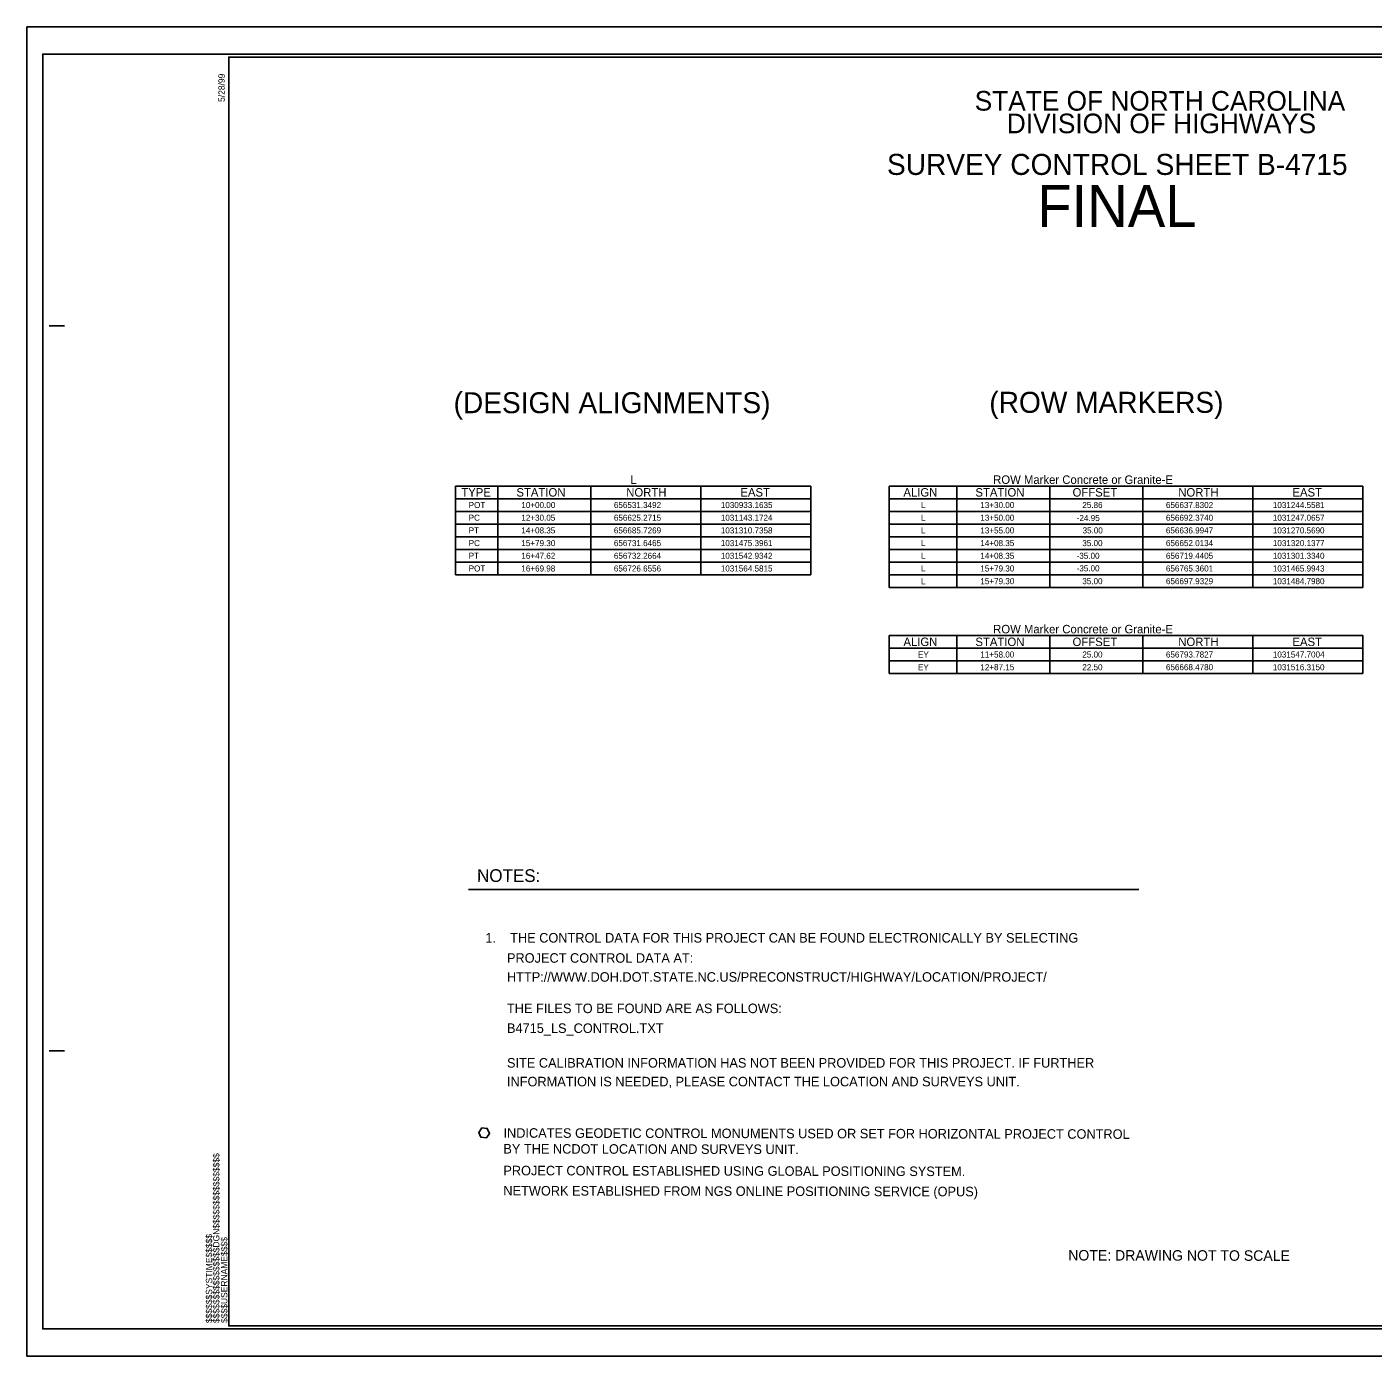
# Model space of a CAD drawing. Extents: x 950817 to 1031536, y 657728 to 805119.
# Drawn here: x 1029852 to 1030966, y 657728 to 658828 of the extents above; entities that cross this region are included whole.
import ezdxf

# ---------------------------------------------------------------- set-up
doc = ezdxf.new("R2010")
doc.units = 0
for name, color, linetype in [('CTL GPS Vertical CELL', 7, 'Continuous'), ('CTL Sheet Border CELL', 7, 'Continuous'), ('CTL Sheet Notes CELL', 7, 'Continuous'), ('CTL Sheet Table Cell', 7, 'Continuous'), ('CTL Sheet Text', 7, 'Continuous'), ('Sheet Cutting Line CELL', 7, 'Continuous'), ('Sheet Plot Border Inside CELL', 7, 'Continuous'), ('Sheet Plot Border Outside CELL', 7, 'Continuous'), ('Sheet Summary CELL', 7, 'Continuous')]:
    doc.layers.add(name, color=color, linetype=linetype)

# ---------------------------------------------------------------- blocks, each defined once
blk = doc.blocks.new('CTL GPS VERTICAL')
at = {"layer": 'CTL GPS Vertical CELL'}
blk.add_line((-0.001, 0), (-0.001, 0), dxfattribs=at)
blk.add_lwpolyline([(-0.065, 0.037), (0, 0.074), (0.065, 0.038), (0.064, -0.036), (-0.001, -0.074), (-0.065, -0.038)], close=True, dxfattribs=at)

msp = doc.modelspace()

# ---------------------------------------------------------------- linework, layer by layer
at = {"layer": 'CTL Sheet Notes CELL'}
msp.add_line((1030217, 658114), (1030771.9, 658114), dxfattribs=at)
at = {"layer": 'CTL Sheet Table Cell'}
for p, q in [((1030206.3, 658447.9), (1030500.3, 658447.9)), ((1030206.3, 658447.9), (1030206.3, 658437.4)), ((1030241.3, 658447.9), (1030241.3, 658437.4)), ((1030318.3, 658447.9), (1030318.3, 658437.4)), ((1030409.3, 658447.9), (1030409.3, 658437.4)), ((1030500.3, 658447.9), (1030500.3, 658437.4)), ((1030565.2, 658447.9), (1030957.2, 658447.9)), ((1030565.2, 658447.9), (1030565.2, 658437.4)), ((1030621.2, 658447.9), (1030621.2, 658437.4)), ((1030698.2, 658447.9), (1030698.2, 658437.4)), ((1030775.2, 658447.9), (1030775.2, 658437.4)), ((1030866.2, 658447.9), (1030866.2, 658437.4)), ((1030957.2, 658447.9), (1030957.2, 658437.4)), ((1030206.3, 658437.4), (1030500.3, 658437.4)), ((1030206.3, 658437.4), (1030206.3, 658426.9)), ((1030241.3, 658437.4), (1030241.3, 658426.9)), ((1030318.3, 658437.4), (1030318.3, 658426.9)), ((1030409.3, 658437.4), (1030409.3, 658426.9)), ((1030500.3, 658437.4), (1030500.3, 658426.9)), ((1030565.2, 658437.4), (1030957.2, 658437.4)), ((1030565.2, 658437.4), (1030565.2, 658426.9)), ((1030621.2, 658437.4), (1030621.2, 658426.9)), ((1030698.2, 658437.4), (1030698.2, 658426.9)), ((1030775.2, 658437.4), (1030775.2, 658426.9)), ((1030866.2, 658437.4), (1030866.2, 658426.9)), ((1030957.2, 658437.4), (1030957.2, 658426.9)), ((1030206.3, 658426.9), (1030500.3, 658426.9)), ((1030206.3, 658426.9), (1030206.3, 658416.4)), ((1030241.3, 658426.9), (1030241.3, 658416.4)), ((1030318.3, 658426.9), (1030318.3, 658416.4)), ((1030409.3, 658426.9), (1030409.3, 658416.4)), ((1030500.3, 658426.9), (1030500.3, 658416.4)), ((1030565.2, 658426.9), (1030957.2, 658426.9)), ((1030565.2, 658426.9), (1030565.2, 658416.4)), ((1030621.2, 658426.9), (1030621.2, 658416.4)), ((1030698.2, 658426.9), (1030698.2, 658416.4)), ((1030775.2, 658426.9), (1030775.2, 658416.4)), ((1030866.2, 658426.9), (1030866.2, 658416.4)), ((1030957.2, 658426.9), (1030957.2, 658416.4)), ((1030206.3, 658416.4), (1030500.3, 658416.4)), ((1030206.3, 658416.4), (1030206.3, 658405.9)), ((1030241.3, 658416.4), (1030241.3, 658405.9)), ((1030318.3, 658416.4), (1030318.3, 658405.9)), ((1030409.3, 658416.4), (1030409.3, 658405.9)), ((1030500.3, 658416.4), (1030500.3, 658405.9)), ((1030565.2, 658416.4), (1030957.2, 658416.4)), ((1030565.2, 658416.4), (1030565.2, 658405.9)), ((1030621.2, 658416.4), (1030621.2, 658405.9)), ((1030698.2, 658416.4), (1030698.2, 658405.9)), ((1030775.2, 658416.4), (1030775.2, 658405.9)), ((1030866.2, 658416.4), (1030866.2, 658405.9)), ((1030957.2, 658416.4), (1030957.2, 658405.9)), ((1030206.3, 658405.9), (1030500.3, 658405.9)), ((1030206.3, 658405.9), (1030206.3, 658395.4)), ((1030241.3, 658405.9), (1030241.3, 658395.4)), ((1030318.3, 658405.9), (1030318.3, 658395.4)), ((1030409.3, 658405.9), (1030409.3, 658395.4)), ((1030500.3, 658405.9), (1030500.3, 658395.4)), ((1030565.2, 658405.9), (1030957.2, 658405.9)), ((1030565.2, 658405.9), (1030565.2, 658395.4)), ((1030621.2, 658405.9), (1030621.2, 658395.4)), ((1030698.2, 658405.9), (1030698.2, 658395.4)), ((1030775.2, 658405.9), (1030775.2, 658395.4)), ((1030866.2, 658405.9), (1030866.2, 658395.4)), ((1030957.2, 658405.9), (1030957.2, 658395.4)), ((1030206.3, 658395.4), (1030500.3, 658395.4)), ((1030206.3, 658395.4), (1030206.3, 658384.9)), ((1030241.3, 658395.4), (1030241.3, 658384.9)), ((1030318.3, 658395.4), (1030318.3, 658384.9)), ((1030409.3, 658395.4), (1030409.3, 658384.9)), ((1030500.3, 658395.4), (1030500.3, 658384.9)), ((1030565.2, 658395.4), (1030957.2, 658395.4)), ((1030565.2, 658395.4), (1030565.2, 658384.9)), ((1030621.2, 658395.4), (1030621.2, 658384.9)), ((1030698.2, 658395.4), (1030698.2, 658384.9)), ((1030775.2, 658395.4), (1030775.2, 658384.9)), ((1030866.2, 658395.4), (1030866.2, 658384.9)), ((1030957.2, 658395.4), (1030957.2, 658384.9)), ((1030206.3, 658384.9), (1030500.3, 658384.9)), ((1030206.3, 658384.9), (1030206.3, 658374.4)), ((1030241.3, 658384.9), (1030241.3, 658374.4)), ((1030318.3, 658384.9), (1030318.3, 658374.4)), ((1030409.3, 658384.9), (1030409.3, 658374.4)), ((1030500.3, 658384.9), (1030500.3, 658374.4)), ((1030565.2, 658384.9), (1030957.2, 658384.9)), ((1030565.2, 658384.9), (1030565.2, 658374.4)), ((1030621.2, 658384.9), (1030621.2, 658374.4)), ((1030698.2, 658384.9), (1030698.2, 658374.4)), ((1030775.2, 658384.9), (1030775.2, 658374.4)), ((1030866.2, 658384.9), (1030866.2, 658374.4)), ((1030957.2, 658384.9), (1030957.2, 658374.4)), ((1030206.3, 658374.4), (1030500.3, 658374.4)), ((1030565.2, 658374.4), (1030957.2, 658374.4)), ((1030565.2, 658374.4), (1030565.2, 658363.9)), ((1030621.2, 658374.4), (1030621.2, 658363.9)), ((1030698.2, 658374.4), (1030698.2, 658363.9)), ((1030775.2, 658374.4), (1030775.2, 658363.9)), ((1030866.2, 658374.4), (1030866.2, 658363.9)), ((1030957.2, 658374.4), (1030957.2, 658363.9)), ((1030565.2, 658363.9), (1030957.2, 658363.9)), ((1030565.2, 658324.2), (1030957.2, 658324.2)), ((1030565.2, 658324.2), (1030565.2, 658313.7)), ((1030621.2, 658324.2), (1030621.2, 658313.7)), ((1030698.2, 658324.2), (1030698.2, 658313.7)), ((1030775.2, 658324.2), (1030775.2, 658313.7)), ((1030866.2, 658324.2), (1030866.2, 658313.7)), ((1030957.2, 658324.2), (1030957.2, 658313.7)), ((1030565.2, 658313.7), (1030957.2, 658313.7)), ((1030565.2, 658313.7), (1030565.2, 658303.2)), ((1030621.2, 658313.7), (1030621.2, 658303.2)), ((1030698.2, 658313.7), (1030698.2, 658303.2)), ((1030775.2, 658313.7), (1030775.2, 658303.2)), ((1030866.2, 658313.7), (1030866.2, 658303.2)), ((1030957.2, 658313.7), (1030957.2, 658303.2)), ((1030565.2, 658303.2), (1030957.2, 658303.2)), ((1030565.2, 658303.2), (1030565.2, 658292.7)), ((1030621.2, 658303.2), (1030621.2, 658292.7)), ((1030698.2, 658303.2), (1030698.2, 658292.7)), ((1030775.2, 658303.2), (1030775.2, 658292.7)), ((1030866.2, 658303.2), (1030866.2, 658292.7)), ((1030957.2, 658303.2), (1030957.2, 658292.7)), ((1030565.2, 658292.7), (1030957.2, 658292.7))]:
    msp.add_line(p, q, dxfattribs=at)
at = {"layer": 'Sheet Cutting Line CELL'}
for p, q in [((1031535.6, 658827.9), (1029851.6, 658827.9)), ((1029851.6, 658827.9), (1029851.6, 657727.9)), ((1029851.6, 657727.9), (1031535.6, 657727.9))]:
    msp.add_line(p, q, dxfattribs=at)
at = {"layer": 'Sheet Plot Border Inside CELL'}
msp.add_lwpolyline([(1031531.1, 658805.4), (1029864.6, 658805.4), (1029864.6, 657750.3), (1031531.1, 657750.3)], close=True, dxfattribs=at)
at = {"layer": 'Sheet Plot Border Outside CELL'}
msp.add_lwpolyline([(1031535.6, 658827.9), (1029851.6, 658827.9), (1029851.6, 657727.9), (1031535.6, 657727.9)], close=True, dxfattribs=at)
at = {"layer": 'Sheet Summary CELL'}
for p, q in [((1030018.6, 658802.9), (1030018.6, 658762.4)), ((1030768.2, 658714.1), (1030768.2, 658714.1)), ((1029870.1, 658580.4), (1029882.6, 658580.4)), ((1029870.1, 657980.4), (1029882.6, 657980.4)), ((1030018.6, 657752.9), (1030018.6, 657752.9)), ((1030018.6, 657752.9), (1030018.6, 657752.9)), ((1030018.6, 657752.9), (1030018.6, 657752.9)), ((1030018.6, 657752.9), (1030018.6, 657752.9)), ((1030018.6, 657752.9), (1030018.6, 657752.9)), ((1030018.6, 657752.9), (1030018.6, 657752.9))]:
    msp.add_line(p, q, dxfattribs=at)
msp.add_lwpolyline([(1031518.6, 658802.9), (1030018.6, 658802.9), (1030018.6, 657752.9), (1031518.6, 657752.9)], close=True, dxfattribs=at)
msp.add_lwpolyline([(1030156.1, 657752.9), (1030156.1, 657752.9)], dxfattribs=at)

# ---------------------------------------------------------------- block references
at = {"layer": 'CTL GPS Vertical CELL', "xscale": 60.500000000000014, "yscale": 60.5, "rotation": -35.82530000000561}
msp.add_blockref('CTL GPS VERTICAL', (1030230, 657912.6), dxfattribs=at)

# ---------------------------------------------------------------- texts
at = {"layer": 'CTL Sheet Border CELL'}
for s, height, p in [('SURVEY CONTROL SHEET B-4715', 17.391, (1030563.4, 658705.4)), ('FINAL', 34.78, (1030687.8, 658662.4)), ('(DESIGN ALIGNMENTS)', 17.391, (1030204.7, 658508.2)), ('(ROW MARKERS)', 17.391, (1030648.1, 658508.5))]:
    msp.add_text(s, height=height, dxfattribs=at).set_placement(p)
msp.add_text('NOTE: DRAWING NOT TO SCALE', height=8.696, rotation=359.8948, dxfattribs=at).set_placement((1030713.4, 657807))
at = {"layer": 'CTL Sheet Notes CELL'}
for s, p in [('L', (1030351, 658449.7)), ('ROW Marker Concrete or Granite-E', (1030651.3, 658449.7)), ('TYPE', (1030211.1, 658439.2)), ('STATION', (1030256.7, 658439.2)), ('NORTH', (1030347.6, 658439.2)), ('EAST', (1030442.1, 658439.2)), ('ALIGN', (1030577, 658439.2)), ('STATION', (1030636.6, 658439.2)), ('OFFSET', (1030717, 658439.2)), ('NORTH', (1030804.5, 658439.2)), ('EAST', (1030899, 658439.2)), ('ROW Marker Concrete or Granite-E', (1030651.3, 658326)), ('ALIGN', (1030577, 658315.5)), ('STATION', (1030636.6, 658315.5)), ('OFFSET', (1030717, 658315.5)), ('NORTH', (1030804.5, 658315.5)), ('EAST', (1030899, 658315.5))]:
    msp.add_text(s, height=7, dxfattribs=at).set_placement(p)
for s, height, rotation, p in [('NOTES:', 10.52, 359.8948, (1030224.1, 658120.3)), ('1.    THE CONTROL DATA FOR THIS PROJECT CAN BE FOUND ELECTRONICALLY BY SELECTING', 7.891, 360, (1030231, 658070.1)), ('PROJECT CONTROL DATA AT:', 7.891, 360, (1030248.9, 658053.4)), ('HTTP://WWW.DOH.DOT.STATE.NC.US/PRECONSTRUCT/HIGHWAY/LOCATION/PROJECT/', 7.891, 360, (1030248.9, 658037.7)), ('THE FILES TO BE FOUND ARE AS FOLLOWS:', 7.891, 360, (1030248.9, 658011.7)), ('B4715_LS_CONTROL.TXT', 7.891, 360, (1030248.9, 657995.3)), ('SITE CALIBRATION INFORMATION HAS NOT BEEN PROVIDED FOR THIS PROJECT. IF FURTHER', 7.891, 360, (1030248.9, 657966.6)), ('INFORMATION IS NEEDED, PLEASE CONTACT THE LOCATION AND SURVEYS UNIT.', 7.891, 360, (1030248.9, 657951.1)), ('INDICATES GEODETIC CONTROL MONUMENTS USED OR SET FOR HORIZONTAL PROJECT CONTROL', 7.891, 359.8948, (1030246, 657908.6)), ('BY THE NCDOT LOCATION AND SURVEYS UNIT.', 7.891, 359.8948, (1030245.9, 657895.5)), ('PROJECT CONTROL ESTABLISHED USING GLOBAL POSITIONING SYSTEM.', 7.891, 359.8948, (1030245.9, 657877.5)), ('NETWORK ESTABLISHED FROM NGS ONLINE POSITIONING SERVICE (OPUS)', 7.891, 359.8948, (1030245.9, 657860.8))]:
    msp.add_text(s, height=height, rotation=rotation, dxfattribs=at).set_placement(p)
at = {"layer": 'CTL Sheet Text'}
for s, p in [('POT', (1030217.2, 658429.7)), ('10+00.00', (1030260.8, 658429.7)), ('656531.3492', (1030337.4, 658429.7)), ('1030933.1635', (1030425.9, 658429.7)), ('L', (1030591.6, 658429.7)), ('13+30.00', (1030640.7, 658429.7)), ('25.86', (1030725.1, 658429.7)), ('656637.8302', (1030794.3, 658429.7)), ('1031244.5581', (1030882.8, 658429.7)), ('PC ', (1030217.2, 658419.2)), ('PT ', (1030217.2, 658408.7)), ('12+30.05', (1030260.8, 658419.2)), ('14+08.35', (1030260.8, 658408.7)), ('656625.2715', (1030337.4, 658419.2)), ('656685.7269', (1030337.4, 658408.7)), ('1031143.1724', (1030425.9, 658419.2)), ('1031310.7358', (1030425.9, 658408.7)), ('L', (1030591.6, 658419.2)), ('L', (1030591.6, 658408.7)), ('13+50.00', (1030640.7, 658419.2)), ('13+55.00', (1030640.7, 658408.7)), ('-24.95', (1030720.5, 658419)), ('35.00', (1030725.3, 658408.7)), ('656692.3740', (1030794.3, 658419.2)), ('656636.9947', (1030794.3, 658408.7)), ('1031247.0657', (1030882.8, 658419.2)), ('1031270.5690', (1030882.8, 658408.7)), ('PC ', (1030217.2, 658398.2)), ('15+79.30', (1030260.8, 658398.2)), ('656731.6465', (1030337.4, 658398.2)), ('1031475.3961', (1030425.9, 658398.2)), ('L', (1030591.6, 658398.2)), ('14+08.35', (1030640.7, 658398.2)), ('35.00', (1030725.1, 658398.2)), ('656652.0134', (1030794.3, 658398.2)), ('1031320.1377', (1030882.8, 658398.2)), ('PT ', (1030217.2, 658387.7)), ('16+47.62', (1030260.8, 658387.7)), ('656732.2664', (1030337.4, 658387.7)), ('1031542.9342', (1030425.9, 658387.7)), ('L', (1030591.6, 658387.7)), ('14+08.35', (1030640.7, 658387.7)), ('-35.00', (1030720.4, 658387.7)), ('656719.4405', (1030794.3, 658387.7)), ('1031301.3340', (1030882.8, 658387.7)), ('POT', (1030217.2, 658377.2)), ('16+69.98', (1030260.8, 658377.2)), ('656726.6556', (1030337.4, 658377.2)), ('1031564.5815', (1030425.9, 658377.2)), ('L', (1030591.6, 658377.2)), ('15+79.30', (1030640.7, 658377.2)), ('-35.00', (1030720.4, 658377.3)), ('656765.3601', (1030794.3, 658377.2)), ('1031465.9943', (1030882.8, 658377.2)), ('L', (1030591.6, 658366.7)), ('15+79.30', (1030640.7, 658366.7)), ('35.00', (1030725.1, 658366.7)), ('656697.9329', (1030794.3, 658366.7)), ('1031484.7980', (1030882.8, 658366.7)), ('EY', (1030589.1, 658306)), ('11+58.00', (1030640.7, 658306)), ('25.00', (1030725.1, 658306)), ('656793.7827', (1030794.3, 658306)), ('1031547.7004', (1030882.8, 658306)), ('EY', (1030589.1, 658295.5)), ('12+87.15', (1030640.7, 658295.5)), ('22.50', (1030725.1, 658295.5)), ('656668.4780', (1030794.3, 658295.5)), ('1031516.3150', (1030882.8, 658295.5))]:
    msp.add_text(s, height=5, dxfattribs=at).set_placement(p)
at = {"layer": 'Sheet Summary CELL'}
for s, p in [('5/28/99', (1030015.3, 658765.8)), ('$$$$$$$$$$$$$$$$DGN$$$$$$$$$$$$$$$$', (1030010.9, 657755.2)), ('$$$$$$SYSTIME$$$$$', (1030004.9, 657755.2)), ('$$$$USERNAME$$$$', (1030017.5, 657755.3))]:
    msp.add_text(s, height=5.25, rotation=90, dxfattribs=at).set_placement(p)
for s, p in [('STATE OF NORTH CAROLINA', (1030636, 658758.6)), ('DIVISION OF HIGHWAYS', (1030662.6, 658739.9))]:
    msp.add_text(s, height=16.25, dxfattribs=at).set_placement(p)

doc.saveas('drawing.dxf')
